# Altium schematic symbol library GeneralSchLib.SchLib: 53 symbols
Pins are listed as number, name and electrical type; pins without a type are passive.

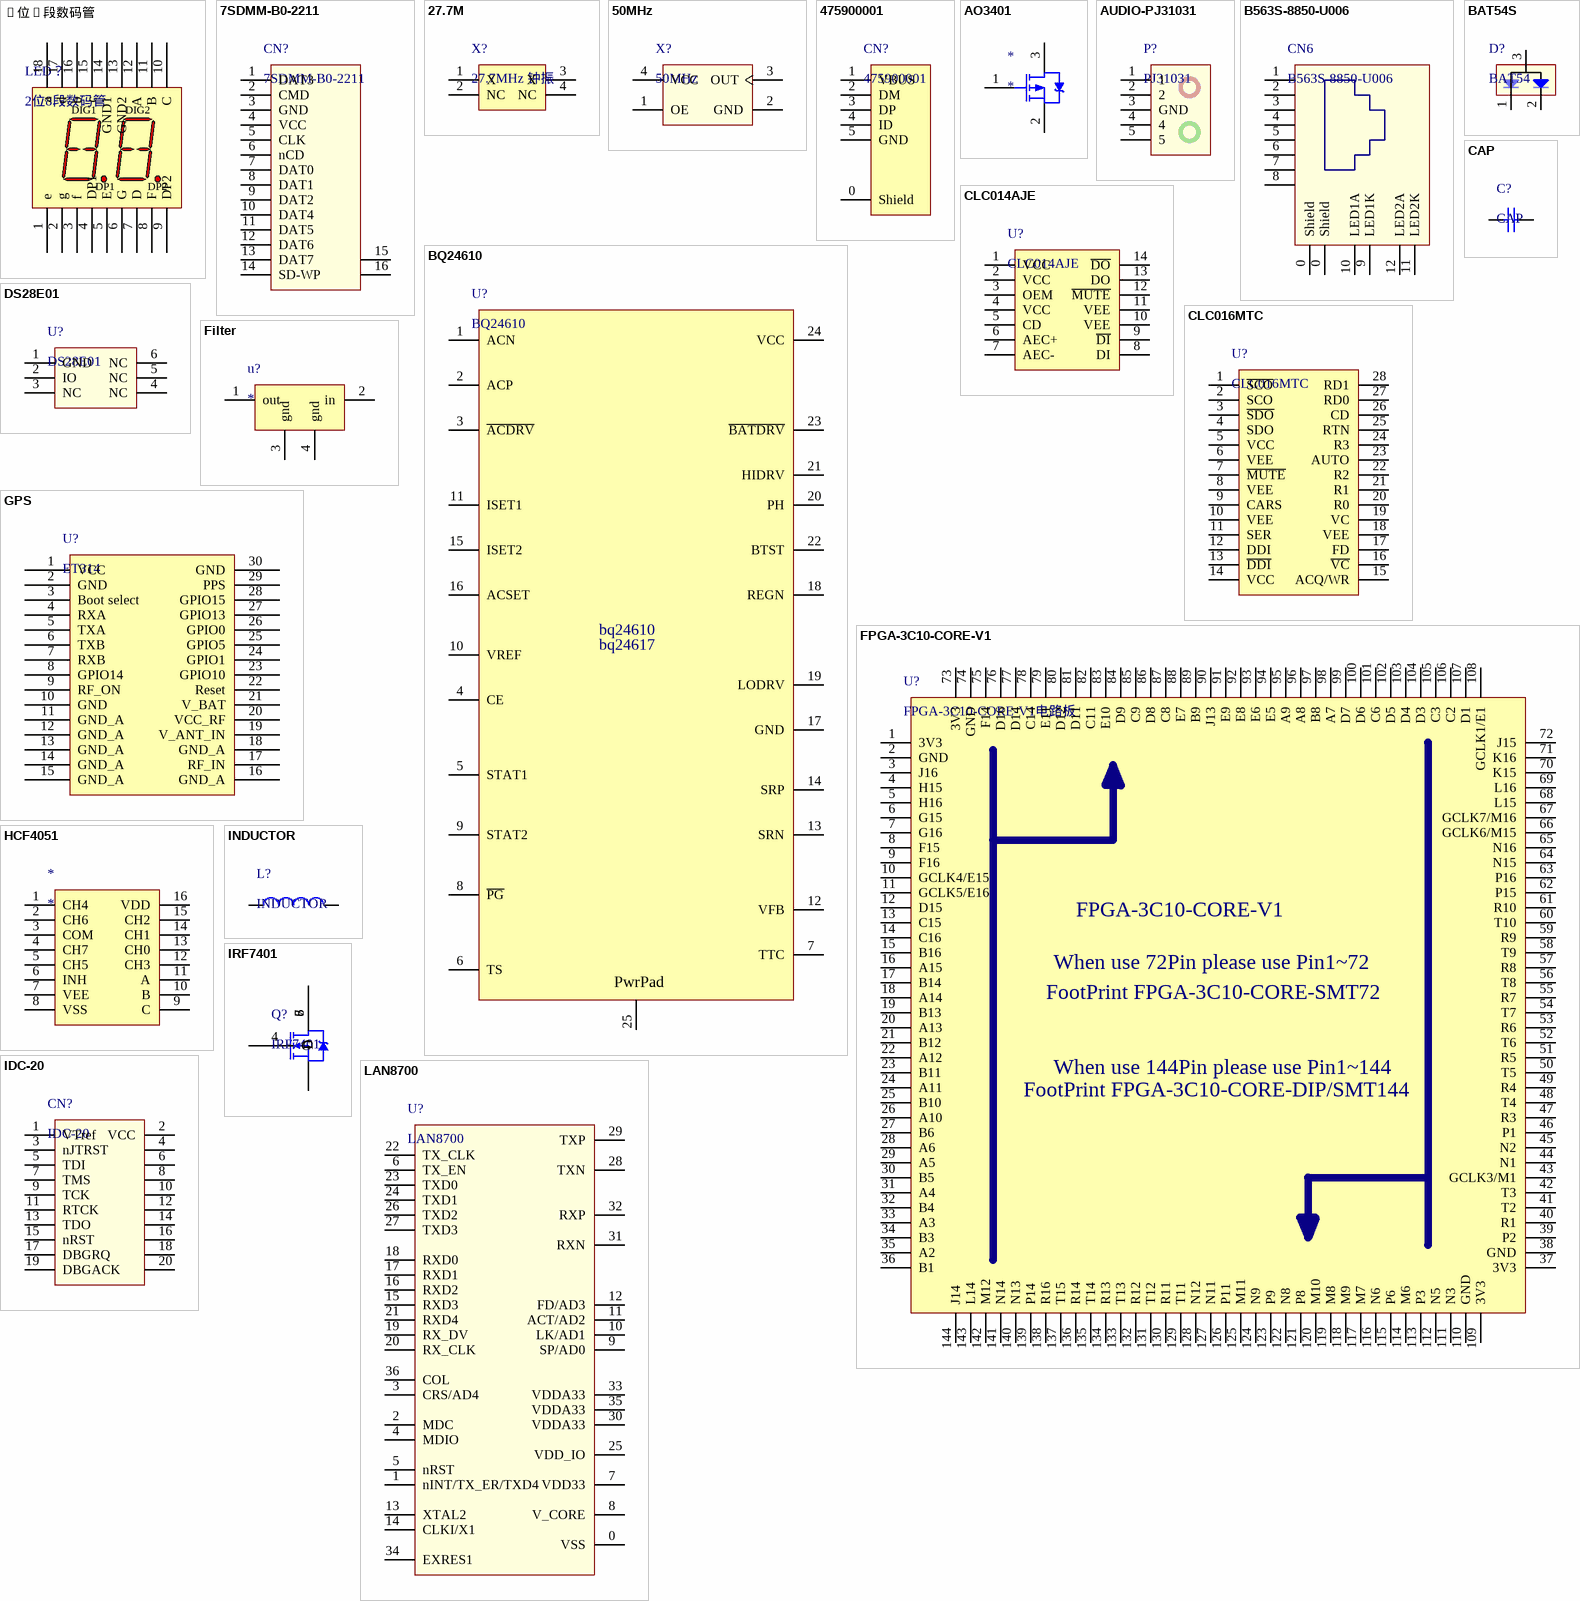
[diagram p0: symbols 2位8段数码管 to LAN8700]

## 2位8段数码管
designator LED？
footprint 2位8段数码管
pins: 1 e, 2 g, 3 f, 4 DP1, 5 E, 6 G, 7 D, 8 F, 9 DP2, 10 C, 11 B, 12 A, 13 GND2, 14 GND1, 15 c, 16 b, 17 d, 18 a

## 7SDMM-B0-2211
designator CN?
pins: 1 DAT3, 2 CMD, 3 GND, 4 VCC, 5 CLK, 6 nCD, 7 DAT0, 8 DAT1, 9 DAT2, 10 DAT4, 11 DAT5, 12 DAT6, 13 DAT7, 14 SD-WP, 15, 16

## 27.7M
designator X?, comment 27.7MHz 钟振
footprint 27.7M
pins: 1 X, 2 NC, 3 X, 4 NC

## 50MHz
designator X?
pins: 1 OE, 2 GND, 3 OUT, 4 VCC

## 475900001
designator CN?
pins: 0 Shield, 1 VBUS, 2 DM, 3 DP, 4 ID, 5 GND

## AO3401
designator *
footprint SOT23A (同：SO-G3/C2.5)
pins: 1 G, 2 S, 3 D

## AUDIO-PJ31031
designator P?, comment PJ31031
footprint AUDIO-PJ31031 (PJ31031双层音频座)
pins: 1, 2, 3 GND, 4, 5

## B563S-8850-U006
designator CN6
pins: 0 Shield, 0 Shield, 1, 2, 3, 4, 5, 6, 7, 8, 9 LED1K, 10 LED1A, 11 LED2K, 12 LED2A

## BAT54S
designator D?, comment BAT54
footprint SOT23A (Footprint not found)
pins: 1, 2, 3

## BQ24610
designator U?
footprint QFN50P400X400-24W6N (QFN, 24-Leads, Body 4x4mm, Pitch 0.5mm, IPC Medium Density)
pins: 1 ACN, 2 ACP, 3 ~{ACDRV}, 4 CE, 5 STAT1, 6 TS, 7 TTC, 8 ~{PG}, 9 STAT2, 10 VREF, 11 ISET1, 12 VFB, 13 SRN, 14 SRP, 15 ISET2, 16 ACSET, 17 GND, 18 REGN, 19 LODRV, 20 PH, 21 HIDRV, 22 BTST, 23 ~{BATDRV}, 24 VCC, 25 PWR_GND

## CAP
designator C?
footprint C-0603
footprint C-0805
footprint C-1210
pins: 1, 2

## CLC014AJE
designator U?
footprint L14_M (Footprint not found)
pins: 1 VCC, 2 VCC, 3 OEM, 4 VCC, 5 CD, 6 AEC+, 7 AEC-, 8 DI, 9 ~{DI}, 10 VEE, 11 VEE, 12 ~{MUTE}, 13 DO, 14 ~{DO}

## CLC016MTC
designator U?
footprint TSSOP28 (Footprint not found)
pins: 1 ~{SCO}, 2 SCO, 3 ~{SDO}, 4 SDO, 5 VCC, 6 VEE, 7 ~{MUTE}, 8 VEE, 9 CARS, 10 VEE, 11 SER, 12 DDI, 13 ~{DDI}, 14 VCC, 15 ACQ/WR, 16 ~{VC}, 17 FD, 18 VEE, 19 VC, 20 R0, 21 R1, 22 R2, 23 AUTO, 24 R3, 25 RTN, 26 CD, 27 RD0, 28 RD1

## DS28E01
designator U?
footprint TSOC6 (Footprint not found)
pins: 1 GND, 2 IO, 3 NC, 4 NC, 5 NC, 6 NC

## Filter
designator u?
pins: 1 out, 2 in, 3 gnd, 4 gnd

## FPGA-3C10-CORE-V1
designator U?, comment FPGA-3C10-CORE-V1电路板
footprint FPGA-3C10-CORE-DIP
footprint FPGA-3C10-CORE-SMT72
footprint FPGA-3C10-CORE-SMT144
pins: 1 3V3, 2 GND, 3 J16, 4 H15, 5 H16, 6 G15, 7 G16, 8 F15, 9 F16, 10 GCLK4/E15, 11 GCLK5/E16, 12 D15, 13 C15, 14 C16, 15 B16, 16 A15, 17 B14, 18 A14, 19 B13, 20 A13, 21 B12, 22 A12, 23 B11, 24 A11, 25 B10, 26 A10, 27 B6, 28 A6, 29 A5, 30 B5, 31 A4, 32 B4, 33 A3, 34 B3, 35 A2, 36 B1, 37 3V3, 38 GND, 39 P2, 40 R1, 41 T2, 42 T3, 43 GCLK3/M1, 44 N1, 45 N2, 46 P1, 47 R3, 48 T4, 49 R4, 50 T5, 51 R5, 52 T6, 53 R6, 54 T7, 55 R7, 56 T8, 57 R8, 58 T9, 59 R9, 60 T10, 61 R10, 62 P15, 63 P16, 64 N15, 65 N16, 66 GCLK6/M15, 67 GCLK7/M16, 68 L15, 69 L16, 70 K15, 71 K16, 72 J15, 73 3V3, 74 GND, 75 F14, 76 D16, 77 D14, 78 C14, 79 E11, 80 D12, 81 D11, 82 C11, 83 E10, 84 D9, 85 C9, 86 D8, 87 C8, 88 E7, 89 B9, 90 J13, 91 E9, 92 E8, 93 E6, 94 E5, 95 A9, 96 A8, 97 B8, 98 A7, 99 D7, 100 D6, 101 C6, 102 D5, 103 D4, 104 D3, 105 C3, 106 C2, 107 D1, 108 GCLK1/E1, 109 3V3, 110 GND, 111 N3, 112 N5, 113 P3, 114 M6, 115 P6, 116 N6, 117 M7, 118 M9, 119 M8, 120 M10, 121 P8, 122 N8, 123 P9, 124 N9, 125 M11, 126 P11, 127 N11, 128 N12, 129 T11, 130 R11, 131 T12, 132 R12, 133 T13, 134 R13, 135 T14, 136 R14, 137 T15, 138 R16, 139 P14, 140 N13, 141 N14, 142 M12, 143 L14, 144 J14

## GPS
designator U?, comment ET314
pins: 1 VCC, 2 GND, 3 Boot select, 4 RXA, 5 TXA, 6 TXB, 7 RXB, 8 GPIO14, 9 RF_ON, 10 GND, 11 GND_A, 12 GND_A, 13 GND_A, 14 GND_A, 15 GND_A, 16 GND_A, 17 RF_IN, 18 GND_A, 19 V_ANT_IN, 20 VCC_RF, 21 V_BAT, 22 Reset, 23 GPIO10, 24 GPIO1, 25 GPIO5, 26 GPIO0, 27 GPIO13, 28 GPIO15, 29 PPS, 30 GND

## HCF4051
designator *
pins: 1 CH4, 2 CH6, 3 COM, 4 CH7, 5 CH5, 6 INH, 7 VEE, 8 VSS, 9 C, 10 B, 11 A, 12 CH3, 13 CH0, 14 CH1, 15 CH2, 16 VDD

## IDC-20
designator CN?
footprint HDR2X10 (Footprint not found)
pins: 1 VTref, 2 VCC, 3 nJTRST, 4, 5 TDI, 6, 7 TMS, 8, 9 TCK, 10, 11 RTCK, 12, 13 TDO, 14, 15 nRST, 16, 17 DBGRQ, 18, 19 DBGACK, 20

## INDUCTOR
designator L?
footprint L-0603
footprint L-0805
pins: 1, 2

## IRF7401
designator Q?
pins: 1 S, 2 S, 3 S, 4 G, 5 D, 6 D, 7 D, 8 D

## LAN8700
designator U?
footprint QFN50P600X600-36V1M (QFN, 36-Leads, Body 6x6mm, Pitch 0.5mm, IPC Low Density)
pins: 0 VSS, 1 nINT/TX_ER/TXD4, 2 MDC, 3 CRS/AD4, 4 MDIO, 5 nRST, 6 TX_EN, 7 VDD33, 8 V_CORE, 9 SP/AD0, 10 LK/AD1, 11 ACT/AD2, 12 FD/AD3, 13 XTAL2, 14 CLKI/X1, 15 RXD3, 16 RXD2, 17 RXD1, 18 RXD0, 19 RX_DV, 20 RX_CLK, 21 RXD4, 22 TX_CLK, 23 TXD0, 24 TXD1, 25 VDD_IO, 26 TXD2, 27 TXD3, 28 TXN, 29 TXP, 30 VDDA33, 31 RXN, 32 RXP, 33 VDDA33, 34 EXRES1, 35 VDDA33, 36 COL

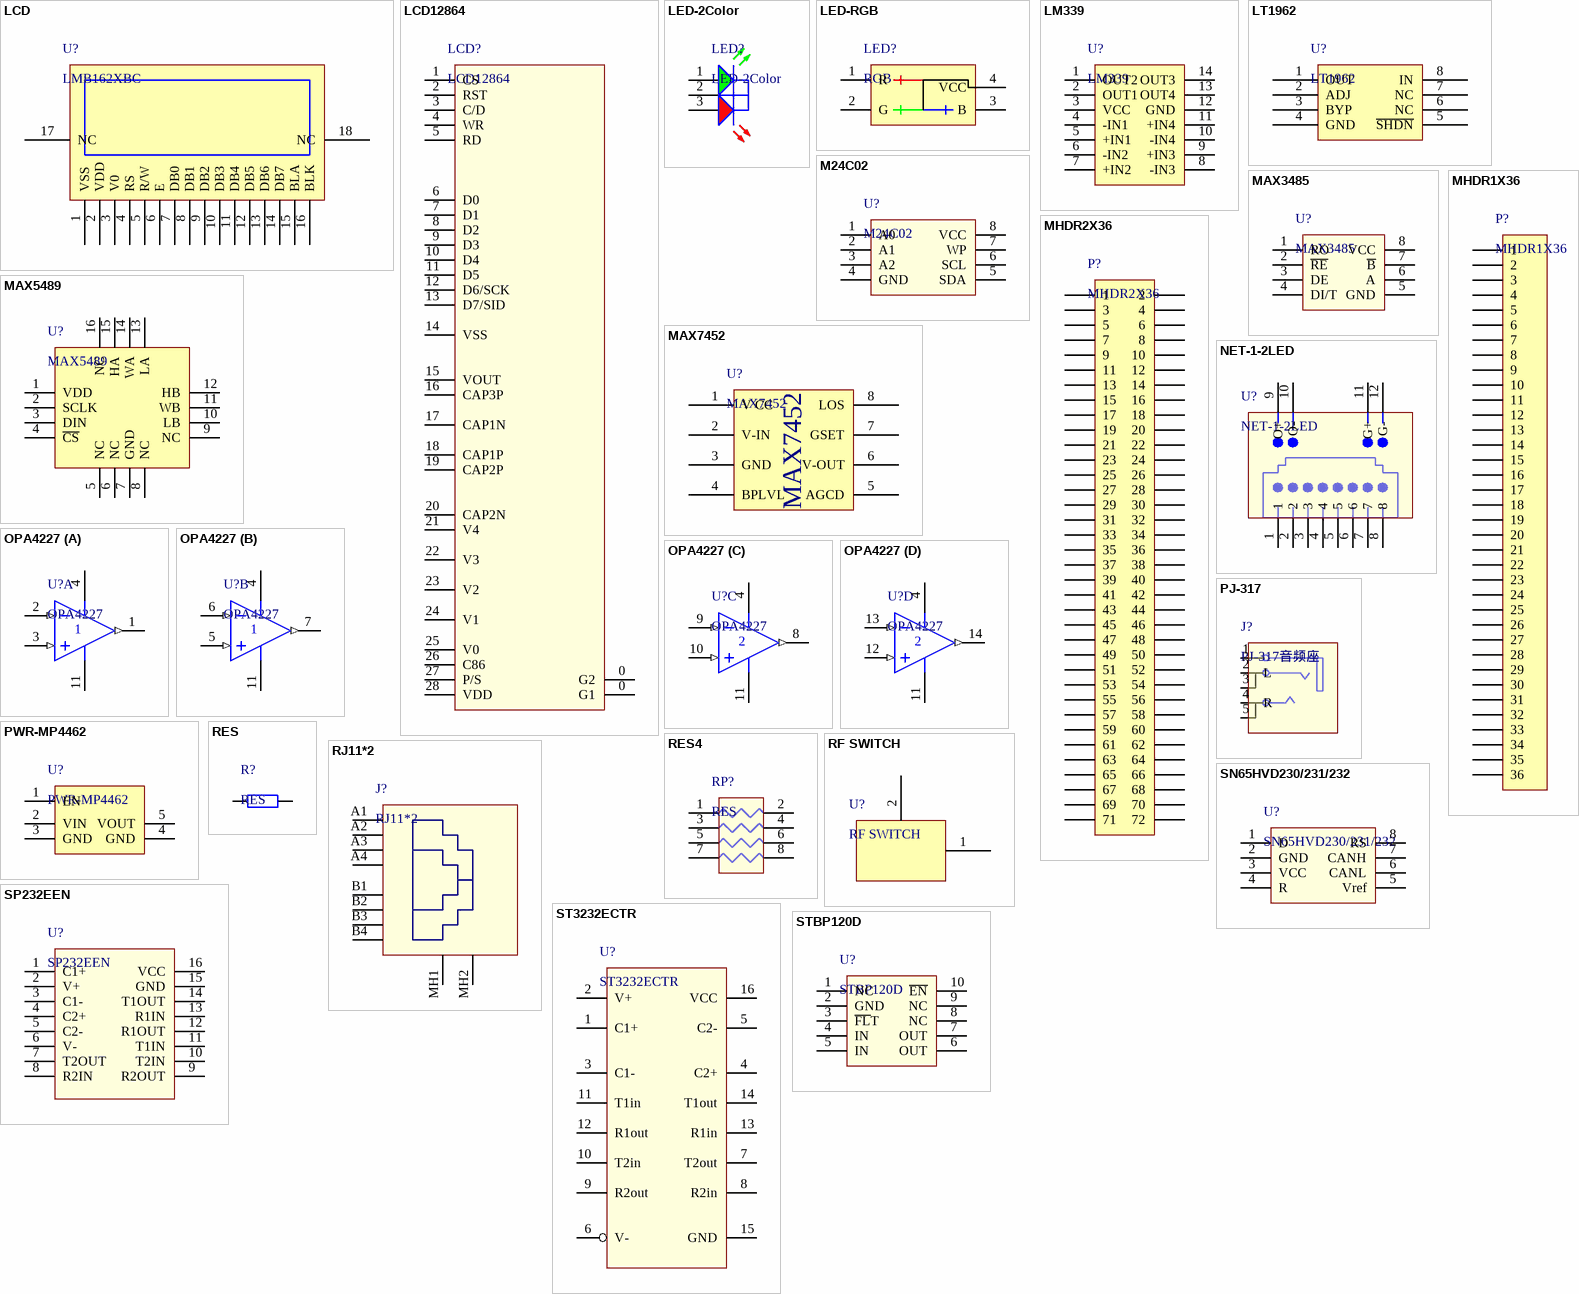
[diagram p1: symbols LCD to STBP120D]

## LCD
designator U?, comment LMB162XBC
footprint LMB162
pins: 1 VSS, 2 VDD, 3 V0, 4 RS, 5 R/W, 6 E, 7 DB0, 8 DB1, 9 DB2, 10 DB3, 11 DB4, 12 DB5, 13 DB6, 14 DB7, 15 BLA, 16 BLK, 17 NC, 18 NC

## LCD12864
designator LCD?
pins: 0 G2, 0 G1, 1 CS, 2 RST, 3 C/D, 4 WR, 5 RD, 6 D0, 7 D1, 8 D2, 9 D3, 10 D4, 11 D5, 12 D6/SCK, 13 D7/SID, 14 VSS, 15 VOUT, 16 CAP3P, 17 CAP1N, 18 CAP1P, 19 CAP2P, 20 CAP2N, 21 V4, 22 V3, 23 V2, 24 V1, 25 V0, 26 C86, 27 P/S, 28 VDD

## LED-2Color
designator LED?
footprint LED-2Color-3mm
pins: 1 A, 2, 3 A

## LED-RGB
designator LED?, comment RGB
footprint LED-RGB
pins: 1 R, 2 G, 3 B, 4 VCC

## LM339
designator U?
footprint SO14_M (14-Pin Small Outline Integrated Circuit 1.27 mm Pitch, IPC Low Density)
pins: 1 OUT2, 2 OUT1, 3 VCC, 4 -IN1, 5 +IN1, 6 -IN2, 7 +IN2, 8 -IN3, 9 +IN3, 10 -IN4, 11 +IN4, 12 GND, 13 OUT4, 14 OUT3

## LT1962
designator U?
pins: 1 OUT, 2 ADJ, 3 BYP, 4 GND, 5 ~{SHDN}, 6 NC, 7 NC, 8 IN

## M24C02
designator U?
pins: 1 A0, 2 A1, 3 A2, 4 GND, 5 SDA, 6 SCL, 7 WP, 8 VCC

## MAX3485
designator U?
pins: 1 RO, 2 ~{RE}, 3 DE, 4 DI/T, 5 GND, 6 A, 7 ~{B}, 8 VCC

## MAX5489
designator U?
footprint QFN100P600X600-16VM (QFN, 16-Leads, Body 6x6 mm, Pitch 1mm, IPC Low Density)
pins: 1 VDD, 2 SCLK, 3 DIN, 4 ~{CS}, 5 NC, 6 NC, 7 GND, 8 NC, 9 NC, 10 LB, 11 WB, 12 HB, 13 LA, 14 WA, 15 HA, 16 NC

## MAX7452
designator U?
pins: 1 V CC, 2 V-IN, 3 GND, 4 BPLVL, 5 AGCD, 6 V-OUT, 7 GSET, 8 LOS

## MHDR1X36
designator P?
footprint 1.27mm-1X36
pins: 1, 2, 3, 4, 5, 6, 7, 8, 9, 10, 11, 12, 13, 14, 15, 16, 17, 18, 19, 20, 21, 22, 23, 24, 25, 26, 27, 28, 29, 30, 31, 32, 33, 34, 35, 36

## MHDR2X36
designator P?
footprint 1.27mm-2x36P
pins: 1, 2, 3, 4, 5, 6, 7, 8, 9, 10, 11, 12, 13, 14, 15, 16, 17, 18, 19, 20, 21, 22, 23, 24, 25, 26, 27, 28, 29, 30, 31, 32, 33, 34, 35, 36, 37, 38, 39, 40, 41, 42, 43, 44, 45, 46, 47, 48, 49, 50, 51, 52, 53, 54, 55, 56, 57, 58, 59, 60, 61, 62, 63, 64, 65, 66, 67, 68, 69, 70, 71, 72

## NET-1-2LED
designator U?
footprint NET-1-2LED
pins: 1, 2, 3, 4, 5, 6, 7, 8, 9 O+, 10 O-, 11 G+, 12 G-

## OPA4227
designator U?
footprint D014_L
part A pins: 1 OUT (out), 2 IN- (in), 3 IN+ (in), 4 V+ (power), 11 V- (power)
part B pins: 4 V+ (power), 5 IN+ (in), 6 IN- (in), 7 OUT (out), 11 V- (power)
part C pins: 4 V+ (power), 8 OUT (out), 9 IN- (in), 10 IN+ (in), 11 V- (power)
part D pins: 4 V+ (power), 11 V- (power), 12 IN+ (in), 13 IN- (in), 14 OUT (out)

## PJ-317
designator J?, comment PJ-317音频座
footprint PJ-317 (音频座)
pins: 1 S (power) "Sleeve (Ground)", 2 L, 3 L, 4 R, 5 R

## PWR-MP4462
designator U?
footprint MP4462-V1 (电路板)
pins: 1 EN, 2 VIN, 3 GND, 4  GND, 5 VOUT

## RES
designator R?
footprint R-0603
footprint R-0805
footprint 1608[0603] (Footprint not found)
pins: 1, 2

## RES4
designator RP?, comment RES
footprint RES4 (RES4-0603)
pins: 1, 2, 3, 4, 5, 6, 7, 8

## RF SWITCH
designator U?
pins: 1, 2

## RJ11*2
designator J?
pins: A1, A2, A3, A4, B1, B2, B3, B4, MH1 DBGACK, MH2 DBGACK

## SN65HVD230/231/232
designator U?
footprint SOP-8_M (Footprint not found)
pins: 1 D, 2 GND, 3 VCC, 4 R, 5 Vref, 6 CANL, 7 CANH, 8 RS

## SP232EEN
designator U?
pins: 1 C1+, 2 V+, 3 C1-, 4 C2+, 5 C2-, 6 V-, 7 T2OUT, 8 R2IN, 9 R2OUT, 10 T2IN, 11 T1IN, 12 R1OUT, 13 R1IN, 14 T1OUT, 15 GND, 16 VCC

## ST3232ECTR
designator U?
footprint SSOP16 (Footprint not found)
pins: 1 C1+, 2 V+, 3 C1-, 4 C2+, 5 C2-, 6 V-, 7 T2out, 8 R2in, 9 R2out, 10 T2in, 11 T1in, 12 R1out, 13 R1in, 14 T1out, 15 GND, 16 VCC

## STBP120D
designator U?
pins: 1 NC, 2 GND, 3 ~{FL}T, 4 IN, 5 IN, 6 OUT, 7 OUT, 8 NC, 9 NC, 10 ~{EN}

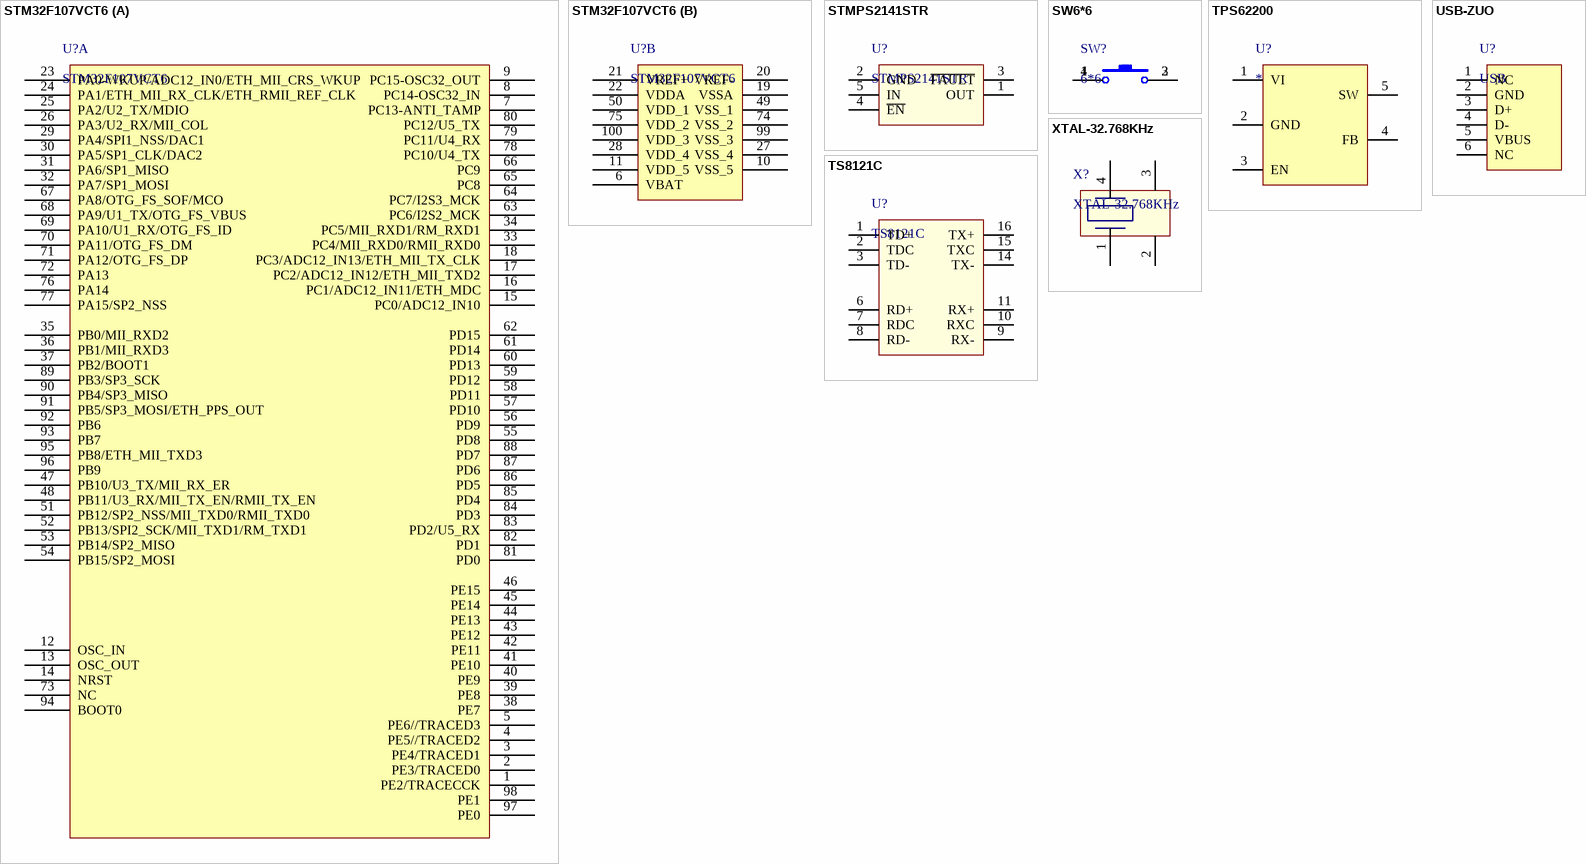
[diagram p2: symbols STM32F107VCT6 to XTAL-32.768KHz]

## STM32F107VCT6
designator U?
footprint LQFP100_L (Footprint not found)
part A pins: 1 PE2/TRACECCK, 2 PE3/TRACED0, 3 PE4/TRACED1, 4 PE5//TRACED2, 5 PE6//TRACED3, 7 PC13-ANTI_TAMP, 8 PC14-OSC32_IN, 9 PC15-OSC32_OUT, 12 OSC_IN, 13 OSC_OUT, 14 NRST, 15 PC0/ADC12_IN10, 16 PC1/ADC12_IN11/ETH_MDC, 17 PC2/ADC12_IN12/ETH_MII_TXD2, 18 PC3/ADC12_IN13/ETH_MII_TX_CLK, 23 PA0-WKUP/ADC12_IN0/ETH_MII_CRS_WKUP, 24 PA1/ETH_MII_RX_CLK/ETH_RMII_REF_CLK, 25 PA2/U2_TX/MDIO, 26 PA3/U2_RX/MII_COL, 29 PA4/SPI1_NSS/DAC1, 30 PA5/SP1_CLK/DAC2, 31 PA6/SP1_MISO, 32 PA7/SP1_MOSI, 33 PC4/MII_RXD0/RMII_RXD0, 34 PC5/MII_RXD1/RM_RXD1, 35 PB0/MII_RXD2, 36 PB1/MII_RXD3, 37 PB2/BOOT1, 38 PE7, 39 PE8, 40 PE9, 41 PE10, 42 PE11, 43 PE12, 44 PE13, 45 PE14, 46 PE15, 47 PB10/U3_TX/MII_RX_ER, 48 PB11/U3_RX/MII_TX_EN/RMII_TX_EN, 51 PB12/SP2_NSS/MII_TXD0/RMII_TXD0, 52 PB13/SPI2_SCK/MII_TXD1/RM_TXD1, 53 PB14/SP2_MISO, 54 PB15/SP2_MOSI, 55 PD8, 56 PD9, 57 PD10, 58 PD11, 59 PD12, 60 PD13, 61 PD14, 62 PD15, 63 PC6/I2S2_MCK, 64 PC7/I2S3_MCK, 65 PC8, 66 PC9, 67 PA8/OTG_FS_SOF/MCO, 68 PA9/U1_TX/OTG_FS_VBUS, 69 PA10/U1_RX/OTG_FS_ID, 70 PA11/OTG_FS_DM, 71 PA12/OTG_FS_DP, 72 PA13, 73 NC, 76 PA14, 77 PA15/SP2_NSS, 78 PC10/U4_TX, 79 PC11/U4_RX, 80 PC12/U5_TX, 81 PD0, 82 PD1, 83 PD2/U5_RX, 84 PD3, 85 PD4, 86 PD5, 87 PD6, 88 PD7, 89 PB3/SP3_SCK, 90 PB4/SP3_MISO, 91 PB5/SP3_MOSI/ETH_PPS_OUT, 92 PB6, 93 PB7, 94 BOOT0, 95 PB8/ETH_MII_TXD3, 96 PB9, 97 PE0, 98 PE1
part B pins: 6 VBAT, 10 VSS_5, 11 VDD_5, 19 VSSA, 20 VREF-, 21 VREF+, 22 VDDA, 27 VSS_4, 28 VDD_4, 49 VSS_1, 50 VDD_1, 74 VSS_2, 75 VDD_2, 99 VSS_3, 100 VDD_3

## STMPS2141STR
designator U?
pins: 1 OUT, 2 GND, 3 ~{FAULT}, 4 ~{EN}, 5 IN

## SW6*6
designator SW?, comment 6*6
footprint SW6*6-2
footprint SW6*6
pins: 1, 2, 3, 4

## TPS62200
designator U?
footprint SOT-23-5 (Footprint not found)
pins: 1 VI, 2 GND, 3 EN, 4 FB, 5 SW

## TS8121C
designator U?
pins: 1 TD+, 2 TDC, 3 TD-, 6 RD+, 7 RDC, 8 RD-, 9 RX-, 10 RXC, 11 RX+, 14 TX-, 15 TXC, 16 TX+

## USB-ZUO
designator U?, comment USB
footprint USB_Lishi
pins: 1 NC, 2 GND, 3 D+, 4 D-, 5 VBUS, 6 NC

## XTAL-32.768KHz
designator X?
pins: 1, 2, 3, 4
